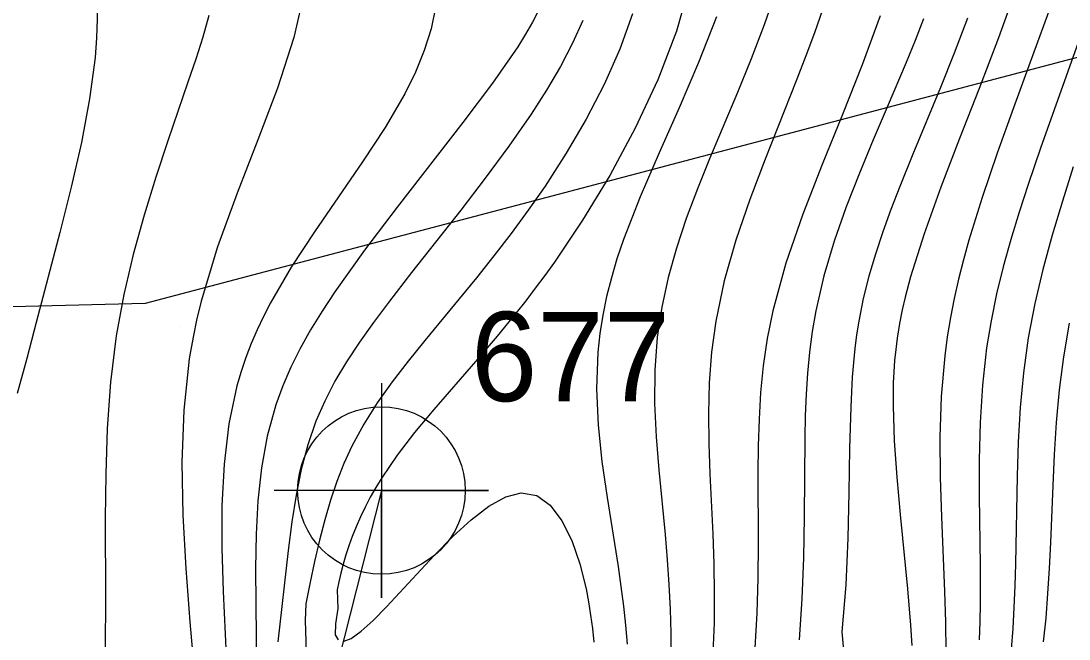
# Model space of a CAD drawing. Extents: x 2602990 to 2605851, y 618069 to 619180.
# Drawn here: x 2603615.54 to 2603644.86, y 618461.27 to 618478.56 of the extents above; entities that cross this region are included whole.
import ezdxf

# ---------------------------------------------------------------- set-up
doc = ezdxf.new("R2010")
doc.units = 0
for name, color, linetype in [('DTM Contours Major', 7, 'Continuous'), ('DTM Contours Minor', 7, 'Continuous'), ('Exist DTM Breakline', 7, 'Continuous'), ('Exist DTM Breakline Cogo Number', 7, 'Continuous'), ('Exist DTM Breakline Cogo Point CELL', 7, 'Continuous'), ('Exist DTM Crownline', 7, 'Continuous'), ('Exist DTM QL2 LIDAR Elevation Point', 7, 'Continuous'), ('Exist Roads EOP', 7, 'Continuous'), ('PH Exist DTM Obscure Area', 7, 'Continuous')]:
    doc.layers.add(name, color=color, linetype=linetype)

# ---------------------------------------------------------------- blocks, each defined once
blk = doc.blocks.new('EXIST DTM BREAKLINE COGO POINT')
at = {"layer": 'Exist DTM Breakline Cogo Point CELL'}
blk.add_lwpolyline([(0, 0.06), (0, -0.06), (0, 0), (0.06, 0), (-0.06, 0)], dxfattribs=at)
blk.add_circle((0, 0), 0.04688, dxfattribs=at)

msp = doc.modelspace()

# ---------------------------------------------------------------- linework, layer by layer
at = {"layer": 'DTM Contours Major'}
for points in [[(2603627.137, 618478.937), (2603627.015, 618478.338), (2603626.828, 618477.737), (2603626.582, 618477.132), (2603626.279, 618476.52), (2603625.731, 618475.578), (2603625.103, 618474.62), (2603623.753, 618472.663), (2603623.104, 618471.67), (2603622.522, 618470.672), (2603622.327, 618470.295), (2603622.148, 618469.917), (2603621.984, 618469.535), (2603621.835, 618469.148), (2603621.702, 618468.756), (2603621.586, 618468.355), (2603621.36, 618467.285), (2603621.227, 618466.163), (2603621.168, 618465.001), (2603621.166, 618463.808), (2603621.201, 618462.593), (2603621.312, 618460.21)], [(2603642.023, 618478.638), (2603641.653, 618477.666), (2603641.266, 618476.704), (2603640.494, 618474.831), (2603640.13, 618473.93), (2603639.882, 618473.29), (2603639.654, 618472.661), (2603639.447, 618472.04), (2603639.264, 618471.419), (2603639.109, 618470.796), (2603638.983, 618470.163), (2603638.923, 618469.783), (2603638.874, 618469.396), (2603638.834, 618469.001), (2603638.801, 618468.597), (2603638.776, 618468.183), (2603638.757, 618467.756), (2603638.726, 618466.598), (2603638.707, 618465.37), (2603638.677, 618464.092), (2603638.617, 618462.785), (2603638.506, 618461.469), (2603638.625, 618460.127)]]:
    msp.add_lwpolyline(points, dxfattribs=at)
at = {"layer": 'DTM Contours Minor'}
for points in [[(2603615.487, 618484.021), (2603615.976, 618483.671), (2603616.408, 618483.214), (2603616.781, 618482.663), (2603617.092, 618482.031), (2603617.34, 618481.331), (2603617.52, 618480.577), (2603617.595, 618480.11), (2603617.646, 618479.628), (2603617.673, 618479.131), (2603617.677, 618478.618), (2603617.658, 618478.09), (2603617.616, 618477.545), (2603617.462, 618476.381), (2603617.234, 618475.165), (2603616.951, 618473.914), (2603616.632, 618472.646), (2603615.966, 618470.128), (2603615.704, 618469.119), (2603615.442, 618468.14)], [(2603645.058, 618481.149), (2603644.693, 618480.001), (2603644.248, 618478.706), (2603643.781, 618477.413), (2603643.311, 618476.13), (2603642.855, 618474.865), (2603642.432, 618473.627), (2603642.06, 618472.424), (2603641.908, 618471.875), (2603641.771, 618471.333), (2603641.65, 618470.795), (2603641.545, 618470.26), (2603641.457, 618469.725), (2603641.386, 618469.188), (2603641.29, 618468.057), (2603641.253, 618466.919), (2603641.26, 618465.789), (2603641.294, 618464.682), (2603641.385, 618462.594), (2603641.409, 618461.738), (2603641.416, 618460.915)], [(2603623.49, 618479.453), (2603623.182, 618478.096), (2603622.724, 618476.686), (2603622.175, 618475.233), (2603621.596, 618473.747), (2603621.046, 618472.239), (2603620.586, 618470.719), (2603620.458, 618470.194), (2603620.367, 618469.762), (2603620.279, 618469.269), (2603620.253, 618469.104), (2603620.096, 618467.671), (2603620.043, 618466.211), (2603620.069, 618464.731), (2603620.153, 618463.241), (2603620.272, 618461.75), (2603620.403, 618460.265)], [(2603634.267, 618479.635), (2603633.881, 618478.282), (2603633.359, 618476.915), (2603632.73, 618475.56), (2603632.02, 618474.241), (2603631.257, 618472.984), (2603630.467, 618471.813), (2603630.199, 618471.443), (2603629.932, 618471.084), (2603629.665, 618470.735), (2603629.397, 618470.396), (2603628.862, 618469.742), (2603628.258, 618469.033), (2603627.094, 618467.69), (2603626.557, 618467.045), (2603626.067, 618466.41), (2603625.635, 618465.781), (2603625.467, 618465.507), (2603625.313, 618465.233), (2603625.17, 618464.959), (2603625.039, 618464.685), (2603624.92, 618464.41), (2603624.811, 618464.136), (2603624.717, 618463.877), (2603624.633, 618463.62), (2603624.557, 618463.365), (2603624.491, 618463.113), (2603624.433, 618462.867), (2603624.394, 618462.645), (2603624.411, 618462.119), (2603624.34, 618461.696), (2603624.333, 618461.385), (2603624.42, 618461.242)], [(2603636.668, 618479.425), (2603636.339, 618478.456), (2603635.973, 618477.5), (2603635.585, 618476.557), (2603634.803, 618474.704), (2603634.467, 618473.867), (2603634.158, 618473.036), (2603633.883, 618472.208), (2603633.651, 618471.38), (2603633.468, 618470.55), (2603633.342, 618469.716), (2603633.274, 618468.789), (2603633.27, 618467.859), (2603633.312, 618466.929), (2603633.386, 618466.005), (2603633.563, 618464.193), (2603633.624, 618463.485), (2603633.672, 618462.789), (2603633.706, 618462.105), (2603633.724, 618461.432), (2603633.724, 618460.768)], [(2603643.393, 618479.502), (2603642.889, 618478.092), (2603642.349, 618476.674), (2603641.803, 618475.271), (2603641.282, 618473.908), (2603640.815, 618472.609), (2603640.432, 618471.398), (2603640.283, 618470.838), (2603640.199, 618470.477), (2603640.122, 618470.092), (2603640.055, 618469.682), (2603640.015, 618469.369), (2603639.984, 618469.058), (2603639.962, 618468.746), (2603639.948, 618468.433), (2603639.941, 618468.116), (2603639.941, 618467.796), (2603639.974, 618466.813), (2603640.046, 618465.794), (2603640.141, 618464.754), (2603640.348, 618462.668), (2603640.43, 618461.653), (2603640.463, 618461.085)], [(2603630.026, 618478.857), (2603629.857, 618478.532), (2603629.662, 618478.194), (2603629.441, 618477.84), (2603628.738, 618476.823), (2603627.907, 618475.717), (2603626.065, 618473.353), (2603625.156, 618472.153), (2603624.323, 618470.979), (2603623.971, 618470.443), (2603623.648, 618469.915), (2603623.356, 618469.393), (2603623.095, 618468.872), (2603622.868, 618468.348), (2603622.675, 618467.819), (2603622.435, 618466.948), (2603622.273, 618466.054), (2603622.174, 618465.137), (2603622.125, 618464.199), (2603622.109, 618463.241), (2603622.113, 618462.264), (2603622.13, 618460.379)], [(2603637.969, 618478.877), (2603637.743, 618478.231), (2603637.502, 618477.586), (2603637.25, 618476.936), (2603636.359, 618474.699), (2603635.931, 618473.564), (2603635.544, 618472.426), (2603635.219, 618471.291), (2603634.98, 618470.164), (2603634.864, 618469.295), (2603634.801, 618468.435), (2603634.78, 618467.581), (2603634.79, 618466.734), (2603634.82, 618465.893), (2603634.895, 618464.208), (2603634.923, 618463.365), (2603634.937, 618462.531), (2603634.932, 618461.706), (2603634.903, 618460.893)], [(2603620.804, 618478.714), (2603620.631, 618478.114), (2603620.434, 618477.494), (2603620.216, 618476.851), (2603619.65, 618475.212), (2603619.313, 618474.193), (2603618.986, 618473.131), (2603618.684, 618472.032), (2603618.421, 618470.904), (2603618.211, 618469.753), (2603618.051, 618468.452), (2603617.958, 618467.154), (2603617.915, 618465.88), (2603617.904, 618464.652), (2603617.91, 618462.421), (2603617.896, 618461.004)], [(2603631.266, 618478.575), (2603630.978, 618477.937), (2603630.636, 618477.285), (2603630.246, 618476.623), (2603629.814, 618475.95), (2603629.195, 618475.061), (2603628.533, 618474.166), (2603627.845, 618473.272), (2603626.471, 618471.522), (2603625.822, 618470.682), (2603625.404, 618470.122), (2603625.014, 618469.572), (2603624.655, 618469.027), (2603624.329, 618468.48), (2603624.042, 618467.926), (2603623.795, 618467.359), (2603623.568, 618466.701), (2603623.386, 618466.015), (2603623.241, 618465.297), (2603623.122, 618464.542), (2603623.02, 618463.746), (2603622.733, 618461.188)], [(2603632.656, 618478.766), (2603632.299, 618477.775), (2603631.86, 618476.786), (2603631.354, 618475.811), (2603630.798, 618474.859), (2603630.205, 618473.943), (2603629.734, 618473.266), (2603629.254, 618472.615), (2603628.771, 618471.986), (2603628.286, 618471.377), (2603627.803, 618470.786), (2603626.841, 618469.622), (2603626.372, 618469.041), (2603625.927, 618468.462), (2603625.512, 618467.878), (2603625.135, 618467.282), (2603624.802, 618466.667), (2603624.578, 618466.178), (2603624.381, 618465.673), (2603624.204, 618465.148), (2603624.044, 618464.602), (2603623.897, 618464.033), (2603623.758, 618463.439), (2603623.632, 618462.856), (2603623.509, 618462.252), (2603623.497, 618461.783), (2603623.52, 618460.898)], [(2603634.999, 618478.681), (2603634.501, 618477.402), (2603633.954, 618476.129), (2603633.394, 618474.872), (2603632.863, 618473.641), (2603632.399, 618472.447), (2603632.218, 618471.909), (2603632.06, 618471.379), (2603631.926, 618470.855), (2603631.818, 618470.334), (2603631.735, 618469.813), (2603631.68, 618469.291), (2603631.646, 618468.272), (2603631.693, 618467.248), (2603631.798, 618466.23), (2603631.941, 618465.225), (2603632.249, 618463.298), (2603632.329, 618462.736), (2603632.398, 618462.188), (2603632.455, 618461.652), (2603632.5, 618461.126)], [(2603639.578, 618478.706), (2603639.079, 618477.333), (2603638.526, 618475.942), (2603637.959, 618474.546), (2603637.418, 618473.157), (2603636.943, 618471.788), (2603636.574, 618470.451), (2603636.42, 618469.678), (2603636.309, 618468.916), (2603636.235, 618468.164), (2603636.191, 618467.416), (2603636.169, 618466.669), (2603636.161, 618465.921), (2603636.164, 618463.953), (2603636.158, 618462.968), (2603636.133, 618461.988), (2603636.077, 618461.02)], [(2603640.795, 618478.626), (2603640.559, 618478.014), (2603640.308, 618477.399), (2603639.775, 618476.146), (2603639.386, 618475.238), (2603638.999, 618474.308), (2603638.63, 618473.36), (2603638.293, 618472.398), (2603638.004, 618471.427), (2603637.777, 618470.453), (2603637.677, 618469.874), (2603637.602, 618469.293), (2603637.547, 618468.708), (2603637.508, 618468.115), (2603637.484, 618467.512), (2603637.469, 618466.898), (2603637.452, 618464.682), (2603637.435, 618463.539), (2603637.393, 618462.389), (2603637.31, 618461.244)], [(2603645.212, 618478.219), (2603644.07, 618475.007), (2603643.719, 618473.983), (2603643.466, 618473.208), (2603643.233, 618472.443), (2603643.023, 618471.685), (2603642.838, 618470.931), (2603642.683, 618470.175), (2603642.559, 618469.414), (2603642.443, 618468.371), (2603642.379, 618467.324), (2603642.353, 618466.283), (2603642.353, 618465.262), (2603642.378, 618463.323), (2603642.381, 618462.782), (2603642.378, 618462.258), (2603642.369, 618461.746), (2603642.353, 618461.245)], [(2603644.983, 618474.483), (2603644.678, 618473.523), (2603644.391, 618472.566), (2603644.13, 618471.611), (2603643.904, 618470.657), (2603643.723, 618469.7), (2603643.588, 618468.72), (2603643.499, 618467.743), (2603643.444, 618466.777), (2603643.414, 618465.829), (2603643.37, 618463.375), (2603643.351, 618462.752), (2603643.324, 618462.148), (2603643.288, 618461.558), (2603643.241, 618460.982)], [(2603644.871, 618470.106), (2603644.709, 618469.165), (2603644.591, 618468.238), (2603644.507, 618467.327), (2603644.449, 618466.435), (2603644.408, 618465.565), (2603644.344, 618463.97), (2603644.308, 618463.242), (2603644.265, 618462.537), (2603644.211, 618461.853), (2603644.141, 618461.19)], [(2603624.557, 618461.198), (2603624.778, 618461.279), (2603625.061, 618461.483), (2603625.394, 618461.787), (2603625.767, 618462.165), (2603627.107, 618463.607), (2603627.627, 618464.136), (2603628.14, 618464.606), (2603628.635, 618464.988), (2603629.104, 618465.249), (2603629.538, 618465.36), (2603629.972, 618465.281), (2603630.352, 618465.008), (2603630.679, 618464.577), (2603630.954, 618464.02), (2603631.178, 618463.372), (2603631.353, 618462.667), (2603631.423, 618462.303), (2603631.481, 618461.934), (2603631.53, 618461.559), (2603631.571, 618461.179)]]:
    msp.add_lwpolyline(points, dxfattribs=at)
at = {"layer": 'Exist DTM Breakline'}
msp.add_line((2603625.628, 618465.423), (2603620.929, 618446.882), dxfattribs=at)
at = {"layer": 'Exist DTM Crownline'}
msp.add_spline([(2603233.488, 618380.754), (2603285.185, 618400.095), (2603335.457, 618418.629), (2603390.812, 618439.069), (2603440.087, 618457.325), (2603493.996, 618477.231), (2603542.655, 618495.301), (2603600.808, 618516.867), (2603653.659, 618536.362), (2603706.222, 618555.742), (2603764.811, 618577.593), (2603823.52, 618599.847), (2603878.564, 618620.56), (2603937.951, 618643.078), (2603997.369, 618665.789), (2604036.209, 618680.665), (2604055.311, 618688.017)], degree=3, dxfattribs=at)
at = {"layer": 'Exist DTM QL2 LIDAR Elevation Point'}
for p, q in [((2603620, 618470), (2603620, 618470)), ((2603630, 618470), (2603630, 618470)), ((2603640, 618470), (2603640, 618470))]:
    msp.add_line(p, q, dxfattribs=at)
at = {"layer": 'Exist Roads EOP'}
for points in [[(2603230.17, 618389.98), (2603282.929, 618409.597), (2603332.773, 618427.868), (2603388.167, 618448.413), (2603437.203, 618466.721), (2603490.778, 618486.527), (2603539.039, 618504.558), (2603597.451, 618526.156), (2603651.053, 618545.972), (2603705.208, 618566.084), (2603762.02, 618587.183), (2603820.334, 618609.162), (2603876.341, 618629.99), (2603934.909, 618652.28), (2603996.409, 618675.568), (2604033.216, 618689.957), (2604052.01, 618697.199)], [(2604034.633, 618668.486), (2603984.89, 618650.123), (2603936.767, 618631.654), (2603888.195, 618613.335), (2603837.766, 618594.258), (2603782.918, 618573.705), (2603731.939, 618554.39), (2603671.126, 618532.171), (2603621.822, 618514.106), (2603561.545, 618491.877), (2603506.421, 618471.293), (2603452.163, 618451.33), (2603398.364, 618431.316), (2603341.431, 618410.355), (2603281.65, 618388.199), (2603223.033, 618366.475), (2603185.717, 618352.612)]]:
    msp.add_spline(points, degree=3, dxfattribs=at)
at = {"layer": 'PH Exist DTM Obscure Area'}
msp.add_lwpolyline([(2603890.105, 618554.081), (2603884.134, 618554.138), (2603877.564, 618556.245), (2603871.962, 618557.136), (2603864.912, 618553.51), (2603864.071, 618543.545), (2603853.53, 618535.106), (2603836.557, 618528.64), (2603798.765, 618518.118), (2603619.02, 618470.66), (2603609.341, 618470.414), (2603597.75, 618470.282), (2603595.263, 618473.117), (2603594.69, 618475.565), (2603599.712, 618477.668), (2603611.669, 618481.486)], dxfattribs=at)

# ---------------------------------------------------------------- block references
at = {"layer": 'Exist DTM Breakline Cogo Point CELL', "xscale": 50, "yscale": 50}
msp.add_blockref('EXIST DTM BREAKLINE COGO POINT', (2603625.628, 618465.423), dxfattribs=at)

# ---------------------------------------------------------------- texts
at = {"layer": 'Exist DTM Breakline Cogo Number'}
msp.add_text('677', height=2.5, dxfattribs=at).set_placement((2603628.128, 618467.923))

doc.saveas('drawing.dxf')
